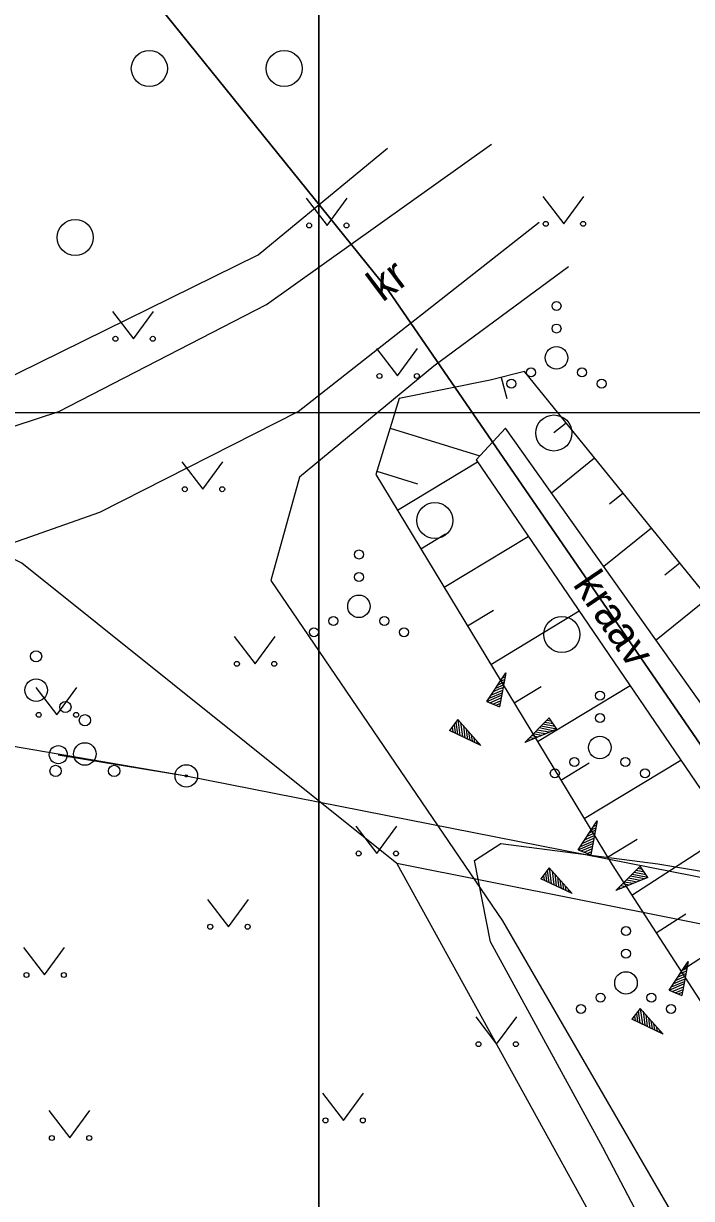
# Model space of a CAD drawing. Extents: x 554947 to 555436, y 6564938 to 6565792.
# Drawn here: x 555223.03 to 555237.85, y 6565130.48 to 6565156.56 of the extents above; entities that cross this region are included whole.
import ezdxf

# ---------------------------------------------------------------- set-up
doc = ezdxf.new("R2010")
doc.units = 0
for name, color, linetype in [('HALJASTUS', 7, 'Continuous'), ('KPOHULIIN', 7, 'Continuous'), ('MPKAABEL', 7, 'Continuous'), ('PIIR', 7, 'Continuous'), ('POST', 7, 'Continuous'), ('PR_SIDE', 7, 'Continuous'), ('PUU', 7, 'Continuous'), ('RELJEEF', 7, 'Continuous'), ('TEE', 7, 'Continuous'), ('VEEKOGU', 7, 'Continuous'), ('VORMISTUS', 7, 'Continuous'), ('VORMISTUS_1', 7, 'Continuous')]:
    doc.layers.add(name, color=color, linetype=linetype)

msp = doc.modelspace()

# ---------------------------------------------------------------- linework, layer by layer
at = {"layer": 'HALJASTUS'}
for p, q in [((555229.306, 6565152.68), (555229.77, 6565152.074)), ((555229.77, 6565152.074), (555230.215, 6565152.68)), ((555234.553, 6565152.717), (555235.017, 6565152.11)), ((555235.017, 6565152.11), (555235.462, 6565152.717)), ((555225.009, 6565150.165), (555225.472, 6565149.558)), ((555225.472, 6565149.558), (555225.918, 6565150.165)), ((555230.866, 6565149.34), (555231.329, 6565148.733)), ((555231.329, 6565148.733), (555231.775, 6565149.34)), ((555226.548, 6565146.826), (555227.012, 6565146.219)), ((555227.012, 6565146.219), (555227.457, 6565146.826)), ((555227.704, 6565142.95), (555228.168, 6565142.343)), ((555228.168, 6565142.343), (555228.613, 6565142.95)), ((555223.308, 6565141.818), (555223.771, 6565141.211)), ((555223.771, 6565141.211), (555224.217, 6565141.818)), ((555230.403, 6565138.741), (555230.867, 6565138.134)), ((555230.867, 6565138.134), (555231.312, 6565138.741)), ((555227.113, 6565137.114), (555227.577, 6565136.508)), ((555227.577, 6565136.508), (555228.022, 6565137.114)), ((555223.035, 6565136.044), (555223.499, 6565135.437)), ((555223.499, 6565135.437), (555223.944, 6565136.044)), ((555233.063, 6565134.508), (555233.526, 6565133.901)), ((555233.526, 6565133.901), (555233.972, 6565134.508)), ((555229.668, 6565132.816), (555230.131, 6565132.209)), ((555230.131, 6565132.209), (555230.577, 6565132.816)), ((555223.598, 6565132.426), (555224.062, 6565131.819)), ((555224.062, 6565131.819), (555224.507, 6565132.426))]:
    msp.add_line(p, q, dxfattribs=at)
for points in [[(555170.849, 6565163.433), (555170.802, 6565162.422), (555180.588, 6565157.338), (555194.166, 6565154.476), (555200.547, 6565151.934), (555210.105, 6565148.383), (555222.421, 6565148.556), (555228.239, 6565151.421), (555231.104, 6565153.786)], [(555235.12, 6565151.155), (555232.135, 6565148.949), (555229.151, 6565146.49), (555228.521, 6565144.196), (555233.66, 6565136.637), (555246.422, 6565114.586), (555255.514, 6565098.946)]]:
    msp.add_lwpolyline(points, dxfattribs=at)
for centre, radius in [((555225.824, 6565155.557), 0.4), ((555228.816, 6565155.557), 0.4), ((555224.181, 6565151.805), 0.4), ((555234.616, 6565152.11), 0.055), ((555235.445, 6565152.11), 0.055), ((555229.369, 6565152.074), 0.055), ((555230.197, 6565152.074), 0.055), ((555234.855, 6565150.286), 0.1), ((555234.855, 6565149.786), 0.1), ((555225.071, 6565149.558), 0.055), ((555225.9, 6565149.558), 0.055), ((555234.855, 6565149.136), 0.25), ((555230.928, 6565148.733), 0.055), ((555231.757, 6565148.733), 0.055), ((555234.29, 6565148.811), 0.1), ((555235.42, 6565148.811), 0.1), ((555233.855, 6565148.561), 0.1), ((555235.855, 6565148.561), 0.1), ((555234.798, 6565147.467), 0.4), ((555226.611, 6565146.219), 0.055), ((555227.44, 6565146.219), 0.055), ((555232.158, 6565145.523), 0.4), ((555230.473, 6565144.77), 0.1), ((555230.473, 6565144.27), 0.1), ((555230.473, 6565143.62), 0.25), ((555229.908, 6565143.295), 0.1), ((555231.038, 6565143.295), 0.1), ((555234.975, 6565142.993), 0.4), ((555229.473, 6565143.045), 0.1), ((555231.473, 6565143.045), 0.1), ((555227.767, 6565142.343), 0.055), ((555228.595, 6565142.343), 0.055), ((555235.818, 6565141.638), 0.1), ((555223.37, 6565141.211), 0.055), ((555224.199, 6565141.211), 0.055), ((555235.818, 6565141.138), 0.1), ((555235.818, 6565140.488), 0.25), ((555235.253, 6565140.163), 0.1), ((555236.383, 6565140.163), 0.1), ((555234.818, 6565139.913), 0.1), ((555236.818, 6565139.913), 0.1), ((555230.466, 6565138.134), 0.055), ((555231.295, 6565138.134), 0.055), ((555227.175, 6565136.508), 0.055), ((555228.004, 6565136.508), 0.055), ((555236.396, 6565136.41), 0.1), ((555236.396, 6565135.91), 0.1), ((555223.098, 6565135.437), 0.055), ((555223.927, 6565135.437), 0.055), ((555236.396, 6565135.26), 0.25), ((555235.831, 6565134.935), 0.1), ((555236.961, 6565134.935), 0.1), ((555235.396, 6565134.685), 0.1), ((555237.396, 6565134.685), 0.1), ((555233.125, 6565133.901), 0.055), ((555233.954, 6565133.901), 0.055), ((555229.73, 6565132.209), 0.055), ((555230.559, 6565132.209), 0.055), ((555223.661, 6565131.819), 0.055), ((555224.49, 6565131.819), 0.055)]:
    msp.add_circle(centre, radius, dxfattribs=at)
at = {"layer": 'KPOHULIIN'}
msp.add_lwpolyline([(555148.701, 6565153.258), (555226.644, 6565139.855), (555319.309, 6565121.586)], dxfattribs=at)
at = {"layer": 'MPKAABEL'}
msp.add_lwpolyline([(555252.588, 6565101.946), (555250.157, 6565105.485), (555246.43, 6565112.048), (555243.328, 6565117.686), (555240.248, 6565123.284), (555235.885, 6565131.607), (555233.393, 6565136.173), (555233.034, 6565137.981), (555233.62, 6565138.358), (555237.1, 6565137.907), (555242.704, 6565136.954), (555245.573, 6565136.455), (555256.506, 6565134.49), (555262.887, 6565133.288), (555269.268, 6565132.087), (555280.849, 6565129.896), (555289.168, 6565128.301), (555288.207, 6565123.189), (555286.959, 6565118.589), (555293.983, 6565117.646), (555297.167, 6565117.091)], dxfattribs=at)
at = {"layer": 'PIIR'}
for points in [[(555293.54, 6565286.23), (555256.63, 6565245.54), (555254.61, 6565228.5), (555255.75, 6565226.79), (555261.42, 6565218.27), (555289.11, 6565186.6), (555315.28, 6565149.09), (555315.73, 6565134.86), (555310.07, 6565124.47), (555303.59, 6565115.89), (555291.54, 6565100.48), (555288.85, 6565092.31), (555275.41, 6565088.83), (555273.15, 6565087.34), (555239.11, 6565139), (555231.12, 6565150.64), (555225.89, 6565157.13), (555173.21, 6565166.35), (555173.84, 6565168.77), (555191.64, 6565237.48), (555195.28, 6565271.63)], [(555272.013, 6565013.369), (555140.74, 6565041.04), (555172.58, 6565163.93), (555173.21, 6565166.35), (555225.89, 6565157.13), (555231.12, 6565150.64), (555239.11, 6565139), (555273.15, 6565087.34), (555275.41, 6565088.83), (555288.85, 6565092.31), (555289.83, 6565088.53), (555290.166, 6565088.221)]]:
    msp.add_lwpolyline(points, dxfattribs=at)
at = {"layer": 'POST'}
msp.add_lwpolyline([(555223.805, 6565140.327), (555226.644, 6565139.855)], dxfattribs=at)
for centre, radius in [((555223.805, 6565140.327), 0.2), ((555226.644, 6565139.855), 0.25), ((555226.644, 6565139.855), 0.0234)]:
    msp.add_circle(centre, radius, dxfattribs=at)
at = {"layer": 'PR_SIDE'}
for points in [[(555239.586, 6565136.265), (555231.314, 6565137.915), (555222.994, 6565144.574), (555217.72, 6565147.16), (555203.944, 6565144.9), (555175.818, 6565152.015), (555174.729, 6565152.29), (555157.882, 6565156.552), (555156.917, 6565156.236), (555156.491, 6565155.453), (555155.859, 6565155.17)], [(555231.314, 6565137.915), (555239.586, 6565122.902)]]:
    msp.add_lwpolyline(points, dxfattribs=at)
at = {"layer": 'PUU'}
for centre, radius in [((555223.313, 6565142.51), 0.125), ((555223.313, 6565141.76), 0.25), ((555223.963, 6565141.385), 0.125), ((555224.394, 6565141.092), 0.125), ((555224.394, 6565140.342), 0.25), ((555223.744, 6565139.967), 0.125), ((555225.044, 6565139.967), 0.125)]:
    msp.add_circle(centre, radius, dxfattribs=at)
at = {"layer": 'RELJEEF'}
for p, q in [((555233.631, 6565148.698), (555233.75, 6565148.231)), ((555231.165, 6565147.573), (555233.157, 6565146.962)), ((555235.07, 6565147.687), (555234.798, 6565147.467)), ((555231.328, 6565145.753), (555233.1, 6565146.826)), ((555235.7, 6565146.911), (555234.743, 6565146.135)), ((555230.872, 6565146.617), (555231.771, 6565146.341)), ((555236.33, 6565146.134), (555236.028, 6565145.889)), ((555231.845, 6565144.898), (555232.391, 6565145.228)), ((555232.363, 6565144.042), (555234.229, 6565145.171)), ((555236.959, 6565145.357), (555235.903, 6565144.501)), ((555237.589, 6565144.58), (555237.257, 6565144.311)), ((555238.219, 6565143.803), (555237.063, 6565142.867)), ((555232.881, 6565143.187), (555233.454, 6565143.534)), ((555233.398, 6565142.331), (555235.357, 6565143.516)), ((555233.311, 6565141.505), (555233.731, 6565142.145)), ((555233.731, 6565142.145), (555233.591, 6565141.39)), ((555233.606, 6565141.955), (555233.706, 6565141.995)), ((555233.656, 6565142.03), (555233.716, 6565142.055)), ((555233.706, 6565142.105), (555233.726, 6565142.115)), ((555233.411, 6565141.655), (555233.661, 6565141.76)), ((555233.461, 6565141.73), (555233.586, 6565141.785)), ((555233.511, 6565141.805), (555233.681, 6565141.88)), ((555233.561, 6565141.88), (555233.691, 6565141.94)), ((555233.586, 6565141.785), (555233.671, 6565141.82)), ((555233.916, 6565141.475), (555234.518, 6565141.84)), ((555234.434, 6565140.62), (555236.486, 6565141.861)), ((555233.311, 6565141.505), (555233.636, 6565141.645)), ((555233.311, 6565141.505), (555233.591, 6565141.39)), ((555233.311, 6565141.505), (555233.311, 6565141.505)), ((555233.361, 6565141.58), (555233.646, 6565141.7)), ((555233.376, 6565141.48), (555233.626, 6565141.585)), ((555233.441, 6565141.45), (555233.616, 6565141.525)), ((555233.511, 6565141.425), (555233.606, 6565141.465)), ((555233.576, 6565141.4), (555233.591, 6565141.405)), ((555232.669, 6565141.104), (555232.484, 6565140.864)), ((555232.584, 6565140.994), (555232.609, 6565140.809)), ((555232.624, 6565141.049), (555232.659, 6565140.779)), ((555232.669, 6565141.104), (555233.174, 6565140.534)), ((555232.669, 6565141.104), (555232.714, 6565140.754)), ((555232.669, 6565141.104), (555232.669, 6565141.104)), ((555232.729, 6565141.039), (555232.769, 6565140.729)), ((555232.789, 6565140.969), (555232.824, 6565140.704)), ((555234.149, 6565140.599), (555234.689, 6565141.144)), ((555234.859, 6565140.894), (555234.509, 6565140.959)), ((555234.819, 6565140.949), (555234.554, 6565141.004)), ((555234.779, 6565141.009), (555234.594, 6565141.044)), ((555234.739, 6565141.069), (555234.639, 6565141.089)), ((555234.699, 6565141.129), (555234.679, 6565141.129)), ((555234.859, 6565140.894), (555234.689, 6565141.144)), ((555233.174, 6565140.534), (555232.484, 6565140.864)), ((555232.494, 6565140.879), (555232.499, 6565140.859)), ((555232.539, 6565140.934), (555232.554, 6565140.834)), ((555232.849, 6565140.904), (555232.864, 6565140.764)), ((555232.864, 6565140.764), (555232.879, 6565140.674)), ((555232.904, 6565140.834), (555232.934, 6565140.649)), ((555232.964, 6565140.769), (555232.984, 6565140.624)), ((555233.024, 6565140.699), (555233.039, 6565140.599)), ((555234.859, 6565140.894), (555234.149, 6565140.599)), ((555234.359, 6565140.684), (555234.254, 6565140.704)), ((555234.439, 6565140.719), (555234.299, 6565140.749)), ((555234.524, 6565140.754), (555234.339, 6565140.789)), ((555234.474, 6565140.814), (555234.384, 6565140.834)), ((555234.689, 6565140.824), (555234.424, 6565140.874)), ((555234.774, 6565140.859), (555234.469, 6565140.919)), ((555234.609, 6565140.789), (555234.474, 6565140.814)), ((555234.859, 6565140.894), (555234.859, 6565140.894)), ((555233.084, 6565140.634), (555233.094, 6565140.569)), ((555233.144, 6565140.564), (555233.149, 6565140.544)), ((555234.189, 6565140.614), (555234.174, 6565140.619)), ((555234.274, 6565140.649), (555234.214, 6565140.664)), ((555235.469, 6565138.909), (555237.614, 6565140.207)), ((555234.952, 6565139.764), (555235.581, 6565140.145)), ((555235.336, 6565138.215), (555235.756, 6565138.855)), ((555235.586, 6565138.59), (555235.716, 6565138.65)), ((555235.756, 6565138.855), (555235.616, 6565138.1)), ((555235.631, 6565138.665), (555235.731, 6565138.705)), ((555235.681, 6565138.74), (555235.741, 6565138.765)), ((555235.731, 6565138.815), (555235.751, 6565138.825)), ((555236.525, 6565137.21), (555238.699, 6565138.616)), ((555235.336, 6565138.215), (555235.661, 6565138.355)), ((555235.386, 6565138.29), (555235.671, 6565138.41)), ((555235.436, 6565138.365), (555235.686, 6565138.47)), ((555235.486, 6565138.44), (555235.611, 6565138.495)), ((555235.536, 6565138.515), (555235.706, 6565138.59)), ((555235.611, 6565138.495), (555235.696, 6565138.53)), ((555235.987, 6565138.053), (555236.644, 6565138.451)), ((555235.336, 6565138.215), (555235.616, 6565138.1)), ((555235.336, 6565138.215), (555235.336, 6565138.215)), ((555235.401, 6565138.19), (555235.651, 6565138.295)), ((555235.466, 6565138.16), (555235.641, 6565138.235)), ((555235.536, 6565138.135), (555235.631, 6565138.175)), ((555235.601, 6565138.11), (555235.616, 6565138.115)), ((555234.695, 6565137.814), (555234.51, 6565137.574)), ((555234.695, 6565137.814), (555235.2, 6565137.244)), ((555234.695, 6565137.814), (555234.74, 6565137.464)), ((555234.695, 6565137.814), (555234.695, 6565137.814)), ((555236.174, 6565137.309), (555236.714, 6565137.854)), ((555236.724, 6565137.839), (555236.704, 6565137.839)), ((555236.884, 6565137.604), (555236.714, 6565137.854)), ((555235.2, 6565137.244), (555234.51, 6565137.574)), ((555234.52, 6565137.589), (555234.525, 6565137.569)), ((555234.565, 6565137.644), (555234.58, 6565137.544)), ((555234.61, 6565137.704), (555234.635, 6565137.519)), ((555234.65, 6565137.759), (555234.685, 6565137.489)), ((555234.755, 6565137.749), (555234.795, 6565137.439)), ((555234.815, 6565137.679), (555234.85, 6565137.414)), ((555234.875, 6565137.614), (555234.89, 6565137.474)), ((555236.884, 6565137.604), (555236.174, 6565137.309)), ((555236.714, 6565137.534), (555236.449, 6565137.584)), ((555236.799, 6565137.569), (555236.494, 6565137.629)), ((555236.884, 6565137.604), (555236.534, 6565137.669)), ((555236.844, 6565137.659), (555236.579, 6565137.714)), ((555236.804, 6565137.719), (555236.619, 6565137.754)), ((555236.764, 6565137.779), (555236.664, 6565137.799)), ((555236.884, 6565137.604), (555236.884, 6565137.604)), ((555234.89, 6565137.474), (555234.905, 6565137.384)), ((555234.93, 6565137.544), (555234.96, 6565137.359)), ((555234.99, 6565137.479), (555235.01, 6565137.334)), ((555235.05, 6565137.409), (555235.065, 6565137.309)), ((555235.11, 6565137.344), (555235.12, 6565137.279)), ((555236.214, 6565137.324), (555236.199, 6565137.329)), ((555236.299, 6565137.359), (555236.239, 6565137.374)), ((555236.384, 6565137.394), (555236.279, 6565137.414)), ((555236.464, 6565137.429), (555236.324, 6565137.459)), ((555236.549, 6565137.464), (555236.364, 6565137.499)), ((555236.499, 6565137.524), (555236.409, 6565137.544)), ((555236.634, 6565137.499), (555236.499, 6565137.524)), ((555235.17, 6565137.274), (555235.175, 6565137.254)), ((555237.068, 6565136.371), (555237.725, 6565136.795)), ((555237.611, 6565135.531), (555239.809, 6565136.952)), ((555237.356, 6565135.097), (555237.776, 6565135.737)), ((555237.776, 6565135.737), (555237.636, 6565134.982)), ((555237.556, 6565135.397), (555237.726, 6565135.472)), ((555237.606, 6565135.472), (555237.736, 6565135.532)), ((555237.651, 6565135.547), (555237.751, 6565135.587)), ((555237.701, 6565135.622), (555237.761, 6565135.647)), ((555237.751, 6565135.697), (555237.771, 6565135.707)), ((555237.356, 6565135.097), (555237.681, 6565135.237)), ((555237.406, 6565135.172), (555237.691, 6565135.292)), ((555237.456, 6565135.247), (555237.706, 6565135.352)), ((555237.506, 6565135.322), (555237.631, 6565135.377)), ((555237.631, 6565135.377), (555237.716, 6565135.412)), ((555237.356, 6565135.097), (555237.636, 6565134.982)), ((555237.356, 6565135.097), (555237.356, 6565135.097)), ((555237.421, 6565135.072), (555237.671, 6565135.177)), ((555237.486, 6565135.042), (555237.661, 6565135.117)), ((555237.556, 6565135.017), (555237.651, 6565135.057)), ((555237.621, 6565134.992), (555237.636, 6565134.997)), ((555236.714, 6565134.696), (555236.529, 6565134.456)), ((555236.714, 6565134.696), (555237.219, 6565134.126)), ((555236.714, 6565134.696), (555236.759, 6565134.346)), ((555236.714, 6565134.696), (555236.714, 6565134.696)), ((555237.219, 6565134.126), (555236.529, 6565134.456)), ((555236.539, 6565134.471), (555236.544, 6565134.451)), ((555236.584, 6565134.526), (555236.599, 6565134.426)), ((555236.629, 6565134.586), (555236.654, 6565134.401)), ((555236.669, 6565134.641), (555236.704, 6565134.371)), ((555236.774, 6565134.631), (555236.814, 6565134.321)), ((555236.834, 6565134.561), (555236.869, 6565134.296)), ((555236.894, 6565134.496), (555236.909, 6565134.356)), ((555236.949, 6565134.426), (555236.979, 6565134.241)), ((555236.909, 6565134.356), (555236.924, 6565134.266)), ((555237.009, 6565134.361), (555237.029, 6565134.216)), ((555237.069, 6565134.291), (555237.084, 6565134.191)), ((555237.129, 6565134.226), (555237.139, 6565134.161)), ((555237.189, 6565134.156), (555237.194, 6565134.136))]:
    msp.add_line(p, q, dxfattribs=at)
msp.add_lwpolyline([(555267.243, 6565100.718), (555264.574, 6565104.451), (555253.061, 6565121.25), (555242.65, 6565138.338), (555234.145, 6565148.829), (555233.386, 6565148.636), (555231.367, 6565148.23), (555230.85, 6565146.543), (555236.09, 6565137.882), (555248.799, 6565118.225), (555259.289, 6565103.411), (555261.934, 6565099.868)], dxfattribs=at)
at = {"layer": 'TEE'}
for points in [[(555216.442, 6565145.526), (555223.819, 6565147.942), (555228.422, 6565150.319), (555233.413, 6565153.879)], [(555217.229, 6565143.067), (555224.725, 6565145.706), (555229.126, 6565147.942), (555234.467, 6565152.147)]]:
    msp.add_lwpolyline(points, dxfattribs=at)
at = {"layer": 'VEEKOGU'}
msp.add_lwpolyline([(555265.45, 6565099.986), (555262.604, 6565103.817), (555251.937, 6565120.038), (555239.993, 6565138.74), (555233.721, 6565147.576), (555233.071, 6565146.869), (555239.071, 6565138.07), (555251.323, 6565119.495), (555261.764, 6565103.47), (555264.187, 6565099.861)], dxfattribs=at)
at = {"layer": 'VORMISTUS'}
for points in [[(555039.586, 6564948.913), (555229.586, 6564948.913), (555229.586, 6565223.913), (555039.586, 6565223.913)], [(555039.586, 6565223.913), (555229.586, 6565223.913), (555229.586, 6564948.913), (555039.586, 6564948.913)]]:
    msp.add_lwpolyline(points, close=True, dxfattribs=at)
at = {"layer": 'VORMISTUS_1'}
msp.add_lwpolyline([(555035.188, 6565444.913), (555245.188, 6565444.913), (555245.188, 6565147.913), (555035.188, 6565147.913)], close=True, dxfattribs=at)

# ---------------------------------------------------------------- texts
at = {"layer": 'TEE'}
msp.add_text('kr', height=0.7, rotation=36.9359, dxfattribs=at).set_placement((555230.994, 6565150.356))
at = {"layer": 'VEEKOGU'}
msp.add_text('kraav', height=0.7, rotation=304.2446, dxfattribs=at).set_placement((555235.203, 6565144.104))

doc.saveas('drawing.dxf')
